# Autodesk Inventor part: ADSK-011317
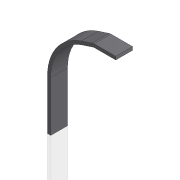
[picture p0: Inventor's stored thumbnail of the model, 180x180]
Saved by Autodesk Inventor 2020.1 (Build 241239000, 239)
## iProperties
Created: 1999-12
Part Number: ADSK-011317
Document SubType Name: Tôlerie
Designer: tgregory
Material: 1.0312 DC05
Density: 1 g/cm^3
Sheet Metal Rule: Stahlblech 1.0312 - DC05 -  10.0 mm
Appearance: Metal-Steel(Polish)
Mass: 222.418 g
Surface Area: 542.563 cm^2
Volume: 222.418 cm^3
Sheet Metal Width: 50,800 mm
Sheet Metal Length: 436,889 mm
Sheet Metal Area: 22193,946 mm^2
Flat Pattern Width: 5.08 cm
Flat Pattern Length: 43.6889 cm
Flat Pattern Area: 221.939 cm^2
Control State: 0
Checked Out: False
Last Check In By: sspink
Last Check In Date: 1999-12-22
Master: False
Shininess: 57.0
Length Units: 11269
Angle Units: 11279
Time Units: 11290
Mass Units: 11283
Length Display Precision: 3
Angle Display Precision: 2
Compacted: True
Cutlength: 17.19
Material Desc: FLAT,S/S,0.375 X 2.00
Material_number: A084622
G_L: 50,8x436,9 mm
Thickness: 10,000 mm
Dimensions: 306,2x50,8x206,8 mm
Mass: 0,222 kg
Semi finished: Stahlblech 1.0312 - DC05 -  10.0 mm
VLT_Material: 1.0312 DC05
Density: 8.03
Volumn: 211.66748494017605
Area: 537.4721205922527
PropertySet Name: Model Information
Author: tgregory
Revision Number: -
Title: ADSK-011317
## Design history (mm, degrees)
node "Solide1"
  node "Extrusion1" dims "d13" = 50.8, "d14" = 0
  node "Bend1" dims "d29" = 10 (= BendRadius), "d33" = 10 (= BendReliefWidth), "d34" = 5 (= BendReliefDepth), "d35" = 20 (= MinimumRemnant), "d36" = 10 (= Thickness), "SeamGap" = 0.00508, "MinimumRemnant" = 20 (= 2 x Thickness), "BendReliefWidth" = 10 (= Thickness)
sketch "Sketch1"
  geometry: L1 (-196.85, -296.194)-(-196.85, -143.794); L2 (-100.32, -10.932)-(-66.675, 0); L3 (-66.675, 0)-(0, 0); L4 (0, 77.093)-(0, -358.409) reference; L5 (-206.85, -296.194)-(-206.85, -143.794); L6 (-103.41, -1.421)-(-68.259, 10); L7 (-68.259, 10)-(0, 10); L8 (-206.85, -296.194)-(-196.85, -296.194); L9 (0, 0)-(0, 10); A1 r 139.7 centre (-57.15, -143.794) between (-100.32, -10.932) and (-196.85, -143.794); A2 r 149.7 centre (-57.15, -143.794) between (-103.41, -1.421) and (-206.85, -143.794)
  constraints: 16 end point, 4 point on circle, 4 tangent, 3 perpendicular, 2 centre point, 1 parallel, 3 other
  dimensions: "d4" = 139.7 radius of A1; "d5" = 108 deg angle of L2 L1; "d6" = 66.675 distance of L3.end L2.end; "d27" = 152.4 distance of L1.end L1.start; "d31" = 196.85 distance between parallel lines of L4 L1; "d32" = 10 distance between parallel lines of L7 L3 (= Thickness)
node "Corps solides"
node "Corps surfaciques"
feature "Definition1"
other parameters: "Thickness" = 10 (derived), "BendReliefDepth" = 5 (= 0.5 x Thickness), "BendReliefDepth" = 5, "Thickness" = 10
